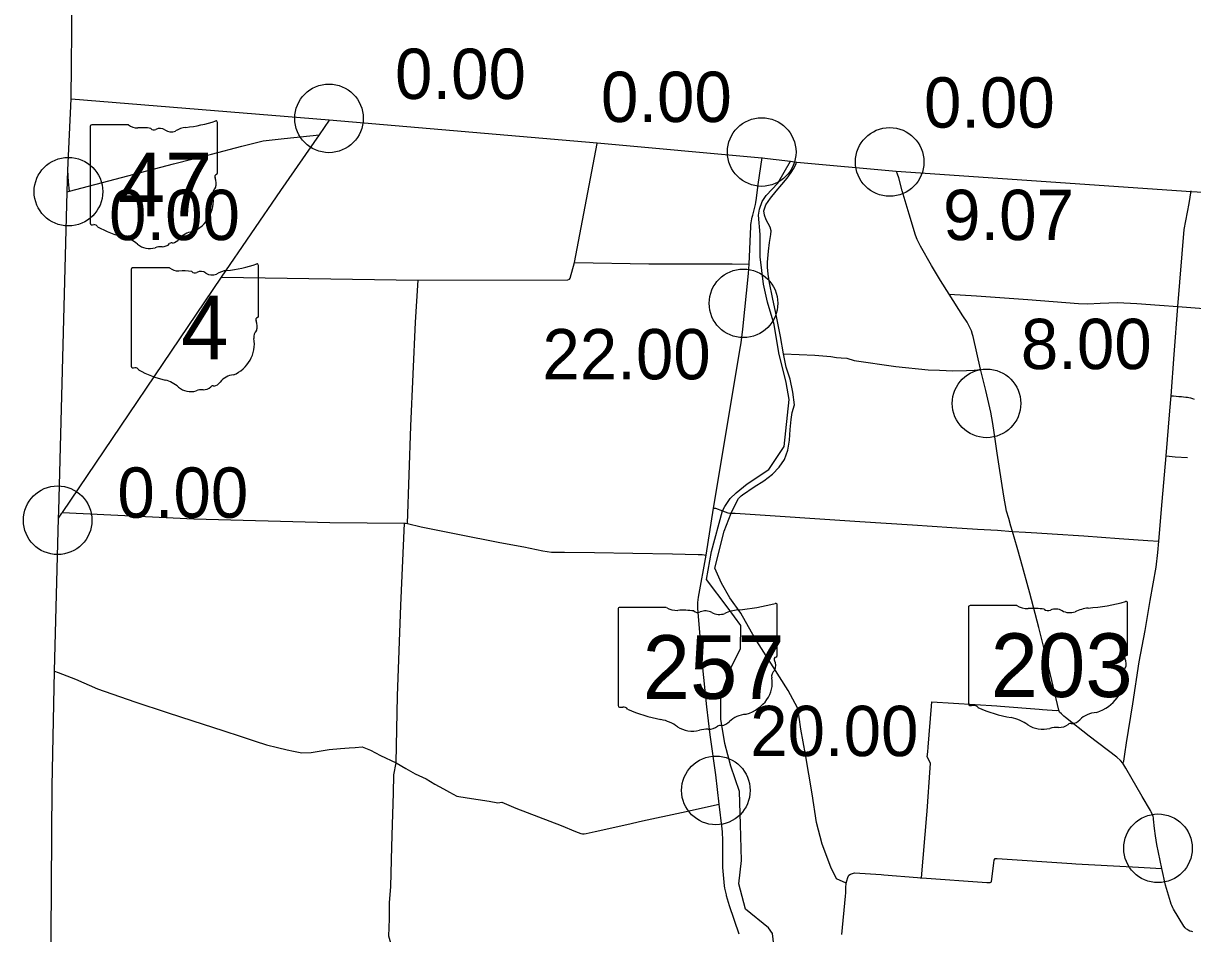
# Model space of a CAD drawing. Extents: x 1729596 to 1934326, y 644115 to 911751.
# Drawn here: x 1759112 to 1784691, y 872786 to 892689 of the extents above; entities that cross this region are included whole.
import ezdxf

# ---------------------------------------------------------------- set-up
doc = ezdxf.new("R2010")
doc.units = 0
for name, color, linetype in [('Default', 7, 'Continuous'), ('GM_X_Adjacent_County', 7, 'Continuous'), ('GM_X_County', 7, 'Continuous'), ('GM_X_County_Road', 7, 'Continuous'), ('GM_X_State_Route', 7, 'Continuous'), ('GM_X_State_Shield', 7, 'Continuous'), ('GM_X_Township', 7, 'Continuous'), ('GM_X_Township_Road', 7, 'Continuous')]:
    doc.layers.add(name, color=color, linetype=linetype)

msp = doc.modelspace()

# ---------------------------------------------------------------- linework, layer by layer
at = {"layer": 'Default'}
for centre in [(1765798, 890612), (1765798, 890612), (1775265, 889876), (1775265, 889876), (1778064, 889660), (1778064, 889660), (1760098, 889010), (1760098, 889010), (1774865, 886568), (1780183, 884380), (1759862, 881825), (1759862, 881825), (1774262, 875917), (1783934, 874652)]:
    msp.add_circle(centre, 750, dxfattribs=at)
at = {"layer": 'GM_X_Adjacent_County'}
msp.add_line((1760161, 891042), (1760364, 911751), dxfattribs=at)
at = {"layer": 'GM_X_County'}
msp.add_lwpolyline([(1759518, 857896), (1759604, 861482), (1759615, 862978), (1759631, 865937), (1759690, 868390), (1759745, 876009), (1759795, 878524), (1759881, 881868), (1759886, 882027), (1760071, 889009), (1760084, 889480), (1760161, 891042), (1765804, 890577), (1771666, 890080), (1775269, 889747), (1775894, 889674), (1776032, 889658), (1778209, 889456), (1784657, 889014), (1789933, 888711), (1791146, 888682), (1797651, 888237), (1803655, 887971)], dxfattribs=at)
at = {"layer": 'GM_X_County_Road'}
for points in [[(1783164, 876512), (1783184, 876554), (1783209, 876711), (1783243, 876961), (1783384, 877811), (1783523, 878729), (1783651, 879411), (1783765, 880071), (1783893, 880796), (1783932, 881116), (1783954, 881366), (1784027, 882233), (1784112, 883231), (1784194, 884219), (1784219, 884544), (1784290, 885451), (1784371, 886499), (1784505, 888183), (1784615, 888751), (1784662, 889026)], [(1779364, 886770), (1779967, 886729), (1781087, 886653), (1782198, 886565), (1782396, 886560), (1782670, 886574), (1783048, 886584), (1783473, 886564), (1783964, 886527), (1784371, 886499), (1786660, 886325), (1787926, 886227), (1788905, 886151), (1789695, 886094), (1789778, 886088), (1790812, 886013), (1791205, 885983), (1792690, 885877), (1793992, 885783), (1794775, 885730), (1796902, 885573), (1797304, 885549), (1797451, 885547), (1797502, 885545)], [(1759969, 881997), (1762841, 881858), (1765814, 881778), (1767451, 881759), (1767471, 881758), (1767516, 881753), (1767813, 881684), (1768617, 881522), (1769536, 881337), (1770062, 881247), (1770477, 881159), (1770666, 881130), (1770953, 881125), (1771606, 881121), (1772443, 881104), (1773313, 881088), (1773587, 881081), (1773877, 881076), (1773962, 881074), (1774048, 881064)], [(1774211, 882090), (1774252, 882089), (1774404, 882033)], [(1774404, 882033), (1774406, 882032), (1774523, 881989), (1774565, 881978), (1774598, 881976), (1774681, 881977), (1777408, 881796), (1778560, 881723), (1779427, 881668), (1779984, 881633), (1780423, 881605), (1780749, 881582)], [(1759795, 878524), (1759874, 878494), (1760252, 878350), (1760733, 878141), (1761552, 877854), (1762256, 877623), (1762819, 877435), (1763473, 877228), (1763875, 877098), (1764180, 876995), (1764428, 876912), (1764673, 876852), (1764882, 876805), (1765024, 876776), (1765203, 876738), (1765411, 876747), (1765804, 876809), (1766052, 876831), (1766236, 876847), (1766368, 876855), (1766526, 876867), (1766703, 876800), (1766927, 876678), (1767271, 876519)], [(1767271, 876519), (1767477, 876397), (1767681, 876278), (1767921, 876172), (1768111, 876051), (1768305, 875950), (1768436, 875882), (1768593, 875793), (1768820, 875758), (1769062, 875716), (1769301, 875685), (1769490, 875642), (1769580, 875657), (1769884, 875528), (1770879, 875150), (1771192, 875019), (1771304, 874972), (1771344, 874966), (1771384, 874967), (1771424, 874974), (1771622, 875018), (1772316, 875174), (1772655, 875249), (1773509, 875437), (1774333, 875620)]]:
    msp.add_lwpolyline(points, dxfattribs=at)
at = {"layer": 'GM_X_State_Route'}
for points in [[(1759881, 881868), (1759956, 881980), (1759969, 881997), (1763443, 887141), (1764744, 889038), (1765591, 890255), (1765808, 890573)], [(1760071, 889009), (1760118, 889022), (1762397, 889618), (1763225, 889831), (1763889, 890004), (1764355, 890118), (1764820, 890175), (1765591, 890255)], [(1774774, 872777), (1774561, 873391), (1774496, 873614), (1774491, 873632), (1774460, 873783), (1774453, 873834), (1774417, 874231), (1774413, 874823), (1774404, 875011), (1774397, 875080), (1774333, 875620), (1774258, 876258), (1774139, 877129), (1774064, 877743), (1773968, 878674), (1773866, 879905), (1773869, 880029), (1773882, 880140), (1774048, 881064), (1774211, 882090), (1774530, 884003), (1774667, 884846), (1774801, 885624), (1774814, 885707), (1774851, 886003), (1774976, 887219), (1774992, 887423), (1775028, 888248), (1775030, 888289), (1775035, 888331), (1775040, 888372), (1775048, 888413), (1775057, 888454), (1775067, 888494), (1775128, 888732), (1775139, 888776), (1775154, 888865), (1775187, 889163), (1775276, 889757)], [(1784699, 872825), (1784673, 872831), (1784633, 872843), (1784596, 872861), (1784578, 872873), (1784561, 872885), (1784531, 872913), (1784502, 872951), (1784275, 873322), (1784260, 873348), (1784235, 873404), (1784225, 873433), (1784211, 873480), (1784162, 873624), (1784100, 873843), (1784021, 874208), (1783910, 874738), (1783876, 874927), (1783859, 875086), (1783838, 875289), (1783833, 875317), (1783827, 875344), (1783809, 875398), (1783786, 875450), (1783772, 875475), (1783588, 875783), (1783232, 876403), (1783164, 876512), (1783115, 876570), (1783035, 876646), (1782427, 877101), (1781907, 877510), (1781873, 877541), (1781822, 877589), (1781780, 877630), (1781764, 877670), (1781516, 878719), (1781330, 879483), (1781130, 880233), (1780935, 880943), (1780851, 881229), (1780749, 881582), (1780714, 881694), (1780668, 881862), (1780620, 882022), (1780562, 882353), (1780462, 883009), (1780418, 883294), (1780375, 883601), (1780321, 883942), (1780275, 884187), (1780166, 884660), (1780054, 885130), (1779891, 885844), (1779879, 885886), (1779851, 885966), (1779818, 886043), (1779756, 886154), (1779666, 886298), (1779364, 886770), (1779176, 887069), (1778977, 887392), (1778738, 887817), (1778667, 887962), (1778627, 888061), (1778487, 888517), (1778336, 889030), (1778262, 889312), (1778237, 889390), (1778211, 889454)]]:
    msp.add_lwpolyline(points, dxfattribs=at)
at = {"layer": 'GM_X_State_Shield'}
for p, q in [((1760571, 890435), (1760571, 888322)), ((1760571, 890435), (1760571, 888322)), ((1761414, 890471), (1760599, 890471)), ((1761414, 890471), (1760599, 890471)), ((1763356, 889418), (1763356, 890524)), ((1763356, 889418), (1763356, 890524)), ((1763355, 889418), (1763356, 889418)), ((1763355, 889418), (1763356, 889418)), ((1762312, 887343), (1761496, 887343)), ((1762312, 887343), (1761496, 887343)), ((1764253, 886290), (1764253, 887395)), ((1764253, 886290), (1764253, 887395)), ((1761469, 887306), (1761469, 885193)), ((1761469, 887306), (1761469, 885193)), ((1764253, 886290), (1764253, 886290)), ((1764253, 886290), (1764253, 886290)), ((1773178, 879920), (1772159, 879920)), ((1773178, 879920), (1772159, 879920)), ((1775605, 878867), (1775605, 879972)), ((1775605, 878867), (1775605, 879972)), ((1779789, 879923), (1779789, 877810)), ((1779789, 879923), (1779789, 877810)), ((1780843, 879960), (1779823, 879960)), ((1780843, 879960), (1779823, 879960)), ((1783269, 878907), (1783269, 880012)), ((1783269, 878907), (1783269, 880012)), ((1772124, 879884), (1772124, 877770)), ((1772124, 879884), (1772124, 877770)), ((1783269, 878907), (1783269, 878907)), ((1783269, 878907), (1783269, 878907)), ((1775604, 878867), (1775605, 878867)), ((1775604, 878867), (1775605, 878867))]:
    msp.add_line(p, q, dxfattribs=at)
for centre, radius, start, end in [((1760603, 890439), 32.3, 98.1301, 188.1301), ((1760603, 890439), 32.3, 98.1301, 188.1301), ((1761608, 890717), 313, 231.6195, 271.1119), ((1761608, 890717), 313, 231.6195, 271.1119), ((1761712, 889285), 1123, 80.4867, 94.9883), ((1761712, 889285), 1123, 80.4867, 94.9883), ((1762741, 889826), 594, 97.3462, 120.7689), ((1762741, 889826), 594, 97.3462, 120.7689), ((1762364, 893352), 2953, 275.8445, 288.9065), ((1762364, 893352), 2953, 275.8445, 288.9065), ((1763325, 890528), 31, 351.8621, 97.738), ((1763325, 890528), 31, 351.8621, 97.738), ((1761967, 890450), 90.3, 219.7921, 297.1024), ((1761967, 890450), 90.3, 219.7921, 297.1024), ((1762100, 890206), 188, 54.4667, 119.1411), ((1762100, 890206), 188, 54.4667, 119.1411), ((1762342, 890541), 226, 233.8562, 294.8282), ((1762342, 890541), 226, 233.8562, 294.8282), ((1763349, 889337), 48, 107.944, 210.337), ((1763349, 889337), 48, 107.944, 210.337), ((1763323, 889414), 33.2, 289.6038, 7.7341), ((1763323, 889414), 33.2, 289.6038, 7.7341), ((1763043, 889197), 288, 340.033, 23.6496), ((1763043, 889197), 288, 340.033, 23.6496), ((1762529, 888815), 739, 292.3089, 8.9858), ((1762529, 888815), 739, 292.3089, 8.9858), ((1763467, 888955), 210, 136.8065, 186.9296), ((1763467, 888955), 210, 136.8065, 186.9296), ((1760604, 888317), 32.5, 171.9584, 258.3066), ((1760604, 888317), 32.5, 171.9584, 258.3066), ((1760609, 888533), 248, 267.339, 280.6039), ((1760609, 888533), 248, 267.339, 280.6039), ((1760659, 888200), 89.5, 29.7484, 93.2717), ((1760659, 888200), 89.5, 29.7484, 93.2717), ((1761790, 890098), 2132, 240.4129, 257.1985), ((1761790, 890098), 2132, 240.4129, 257.1985), ((1762841, 887728), 404, 94.4031, 142.5768), ((1762841, 887728), 404, 94.4031, 142.5768), ((1761154, 887372), 667, 47.1842, 75.836), ((1761154, 887372), 667, 47.1842, 75.836), ((1761876, 888189), 423, 230.7004, 286.2918), ((1761876, 888189), 423, 230.7004, 286.2918), ((1762151, 888031), 226, 268.777, 315.5493), ((1762151, 888031), 226, 268.777, 315.5493), ((1762355, 887826), 63.5, 65.7517, 132.6484), ((1762355, 887826), 63.5, 65.7517, 132.6484), ((1762328, 888117), 239, 282.8732, 323.2771), ((1762328, 888117), 239, 282.8732, 323.2771), ((1762120, 887459), 348, 85.6951, 111.2099), ((1762120, 887459), 348, 85.6951, 111.2099), ((1761501, 887311), 32.3, 98.1301, 188.1301), ((1761501, 887311), 32.3, 98.1301, 188.1301), ((1762506, 887588), 313, 231.6195, 271.1119), ((1762506, 887588), 313, 231.6195, 271.1119), ((1763261, 890224), 2953, 275.8445, 288.9065), ((1763261, 890224), 2953, 275.8445, 288.9065), ((1764222, 887400), 31, 351.8621, 97.738), ((1764222, 887400), 31, 351.8621, 97.738), ((1762610, 886156), 1123, 80.4867, 94.9883), ((1762610, 886156), 1123, 80.4867, 94.9883), ((1762865, 887322), 90.3, 219.7921, 297.1024), ((1762865, 887322), 90.3, 219.7921, 297.1024), ((1762997, 887078), 188, 54.4667, 119.1411), ((1762997, 887078), 188, 54.4667, 119.1411), ((1763239, 887413), 226, 233.8562, 294.8282), ((1763239, 887413), 226, 233.8562, 294.8282), ((1763638, 886697), 594, 97.3462, 120.7689), ((1763638, 886697), 594, 97.3462, 120.7689), ((1764246, 886209), 48, 107.944, 210.337), ((1764246, 886209), 48, 107.944, 210.337), ((1763941, 886069), 288, 340.033, 23.6496), ((1763941, 886069), 288, 340.033, 23.6496), ((1764220, 886285), 33.2, 289.6038, 7.7341), ((1764220, 886285), 33.2, 289.6038, 7.7341), ((1763427, 885686), 739, 292.3089, 8.9858), ((1763427, 885686), 739, 292.3089, 8.9858), ((1764364, 885827), 210, 136.8065, 186.9296), ((1764364, 885827), 210, 136.8065, 186.9296), ((1761501, 885189), 32.5, 171.9584, 258.3066), ((1761501, 885189), 32.5, 171.9584, 258.3066), ((1761506, 885405), 248, 267.339, 280.6039), ((1761506, 885405), 248, 267.339, 280.6039), ((1761557, 885071), 89.5, 29.7484, 93.2717), ((1761557, 885071), 89.5, 29.7484, 93.2717), ((1762687, 886970), 2132, 240.4129, 257.1985), ((1762687, 886970), 2132, 240.4129, 257.1985), ((1762052, 884244), 667, 47.1842, 75.836), ((1762052, 884244), 667, 47.1842, 75.836), ((1763226, 884988), 239, 282.8732, 323.2771), ((1763226, 884988), 239, 282.8732, 323.2771), ((1763738, 884600), 404, 94.4031, 142.5768), ((1763738, 884600), 404, 94.4031, 142.5768), ((1762773, 885061), 423, 230.7004, 286.2918), ((1762773, 885061), 423, 230.7004, 286.2918), ((1763018, 884330), 348, 85.6951, 111.2099), ((1763018, 884330), 348, 85.6951, 111.2099), ((1763049, 884903), 226, 268.777, 315.5493), ((1763049, 884903), 226, 268.777, 315.5493), ((1763253, 884698), 63.5, 65.7517, 132.6484), ((1763253, 884698), 63.5, 65.7517, 132.6484)]:
    msp.add_arc(centre, radius, start, end, dxfattribs=at)
for centre, major_axis, start_param, end_param in [((1772164, 879888), (40.3, 0), 1.712693, 3.28349), ((1772164, 879888), (40.3, 0), 1.712693, 3.28349), ((1773421, 880165), (391, 0), 4.042523, 4.731795), ((1773421, 880165), (391, 0), 4.042523, 4.731795), ((1774365, 882801), (3691, 0), 4.814394, 5.042369), ((1774365, 882801), (3691, 0), 4.814394, 5.042369), ((1775566, 879977), (38.7, 0), 6.141152, 7.989035), ((1775566, 879977), (38.7, 0), 6.141152, 7.989035), ((1779829, 879928), (40.3, 0), 1.712693, 3.28349), ((1779829, 879928), (40.3, 0), 1.712693, 3.28349), ((1781085, 880205), (391, 0), 4.042523, 4.731795), ((1781085, 880205), (391, 0), 4.042523, 4.731795), ((1782030, 882841), (3691, 0), 4.814394, 5.042369), ((1782030, 882841), (3691, 0), 4.814394, 5.042369), ((1783231, 880017), (38.7, 0), 6.141152, 7.989035), ((1783231, 880017), (38.7, 0), 6.141152, 7.989035), ((1773550, 878734), (1404, 0), 1.404758, 1.657858), ((1773550, 878734), (1404, 0), 1.404758, 1.657858), ((1773869, 879899), (113, 0), 3.836095, 5.185415), ((1773869, 879899), (113, 0), 3.836095, 5.185415), ((1774035, 879655), (235, 0), 0.950623, 2.079405), ((1774035, 879655), (235, 0), 0.950623, 2.079405), ((1774337, 879990), (282, 0), 4.081561, 5.145723), ((1774337, 879990), (282, 0), 4.081561, 5.145723), ((1774836, 879275), (743, 0), 1.699011, 2.107814), ((1774836, 879275), (743, 0), 1.699011, 2.107814), ((1781215, 878773), (1404, 0), 1.404758, 1.657858), ((1781215, 878773), (1404, 0), 1.404758, 1.657858), ((1781534, 879939), (113, 0), 3.836095, 5.185415), ((1781534, 879939), (113, 0), 3.836095, 5.185415), ((1781699, 879694), (235, 0), 0.950623, 2.079405), ((1781699, 879694), (235, 0), 0.950623, 2.079405), ((1782002, 880030), (282, 0), 4.081561, 5.145723), ((1782002, 880030), (282, 0), 4.081561, 5.145723), ((1782500, 879314), (743, 0), 1.699011, 2.107814), ((1782500, 879314), (743, 0), 1.699011, 2.107814), ((1783228, 878902), (41.5, 0), 5.05454, 6.418171), ((1783228, 878902), (41.5, 0), 5.05454, 6.418171), ((1775596, 878786), (60, 0), 1.883978, 3.671073), ((1775596, 878786), (60, 0), 1.883978, 3.671073), ((1775214, 878646), (360, 0), 5.934695, 6.695948), ((1775214, 878646), (360, 0), 5.934695, 6.695948), ((1775563, 878863), (41.5, 0), 5.05454, 6.418171), ((1775563, 878863), (41.5, 0), 5.05454, 6.418171), ((1783260, 878825), (60, 0), 1.883978, 3.671073), ((1783260, 878825), (60, 0), 1.883978, 3.671073), ((1782879, 878686), (360, 0), 5.934695, 6.695948), ((1782879, 878686), (360, 0), 5.934695, 6.695948), ((1774572, 878264), (923, 0), 5.101752, 6.440018), ((1774572, 878264), (923, 0), 5.101752, 6.440018), ((1775743, 878404), (262, 0), 2.387724, 3.262537), ((1775743, 878404), (262, 0), 2.387724, 3.262537), ((1782236, 878303), (923, 0), 5.101752, 6.440018), ((1782236, 878303), (923, 0), 5.101752, 6.440018), ((1783408, 878444), (262, 0), 2.387724, 3.262537), ((1783408, 878444), (262, 0), 2.387724, 3.262537), ((1772164, 877766), (40.7, 0), 3.00124, 4.508301), ((1772164, 877766), (40.7, 0), 3.00124, 4.508301), ((1772171, 877982), (310, 0), 4.665946, 4.897461), ((1772171, 877982), (310, 0), 4.665946, 4.897461), ((1772234, 877649), (112, 0), 0.519207, 1.627899), ((1772234, 877649), (112, 0), 0.519207, 1.627899), ((1773647, 879547), (2665, 0), 4.195997, 4.488961), ((1773647, 879547), (2665, 0), 4.195997, 4.488961), ((1779829, 877805), (40.7, 0), 3.00124, 4.508301), ((1779829, 877805), (40.7, 0), 3.00124, 4.508301), ((1779835, 878022), (310, 0), 4.665946, 4.897461), ((1779835, 878022), (310, 0), 4.665946, 4.897461), ((1779899, 877688), (112, 0), 0.519207, 1.627899), ((1779899, 877688), (112, 0), 0.519207, 1.627899), ((1781312, 879587), (2665, 0), 4.195997, 4.488961), ((1781312, 879587), (2665, 0), 4.195997, 4.488961), ((1782626, 877217), (506, 0), 1.647645, 2.488434), ((1782626, 877217), (506, 0), 1.647645, 2.488434), ((1772853, 876821), (834, 0), 0.823519, 1.323587), ((1772853, 876821), (834, 0), 0.823519, 1.323587), ((1774320, 877566), (298, 0), 4.937069, 5.64225), ((1774320, 877566), (298, 0), 4.937069, 5.64225), ((1774961, 877177), (506, 0), 1.647645, 2.488434), ((1774961, 877177), (506, 0), 1.647645, 2.488434), ((1780518, 876861), (834, 0), 0.823519, 1.323587), ((1780518, 876861), (834, 0), 0.823519, 1.323587), ((1781764, 877519), (282, 0), 4.691044, 5.507374), ((1781764, 877519), (282, 0), 4.691044, 5.507374), ((1782019, 877315), (79.4, 0), 1.147584, 2.315152), ((1782019, 877315), (79.4, 0), 1.147584, 2.315152), ((1781985, 877605), (298, 0), 4.937069, 5.64225), ((1781985, 877605), (298, 0), 4.937069, 5.64225), ((1773755, 877638), (529, 0), 4.026481, 4.996735), ((1773755, 877638), (529, 0), 4.026481, 4.996735), ((1774060, 876907), (435, 0), 1.495662, 1.94098), ((1774060, 876907), (435, 0), 1.495662, 1.94098), ((1774099, 877480), (282, 0), 4.691044, 5.507374), ((1774099, 877480), (282, 0), 4.691044, 5.507374), ((1774354, 877275), (79.4, 0), 1.147584, 2.315152), ((1774354, 877275), (79.4, 0), 1.147584, 2.315152), ((1781419, 877678), (529, 0), 4.026481, 4.996735), ((1781419, 877678), (529, 0), 4.026481, 4.996735), ((1781725, 876947), (435, 0), 1.495662, 1.94098), ((1781725, 876947), (435, 0), 1.495662, 1.94098)]:
    msp.add_ellipse(centre, major_axis=major_axis, ratio=0.8, start_param=start_param, end_param=end_param, dxfattribs=at)
at = {"layer": 'GM_X_Township'}
msp.add_lwpolyline([(1775561, 872294), (1775504, 872788), (1775414, 872915), (1774908, 873319), (1774761, 873873), (1774819, 874386), (1774803, 875172), (1774782, 875893), (1774586, 876451), (1774457, 876944), (1774369, 877473), (1774370, 877987), (1774561, 878529), (1774803, 879020), (1774811, 879521), (1774533, 879901), (1774059, 880530), (1774167, 881144), (1774406, 882032), (1774456, 882123), (1774578, 882303), (1774707, 882427), (1774948, 882624), (1775424, 882934), (1775526, 883091), (1775753, 883439), (1775862, 884465), (1775797, 884834), (1775636, 885483), (1775537, 886105), (1775391, 886594), (1775307, 886986), (1775234, 887582), (1775230, 888073), (1775193, 888494), (1775219, 888624), (1775271, 888791), (1775360, 888928), (1775618, 889192), (1775894, 889674)], dxfattribs=at)
at = {"layer": 'GM_X_Township_Road'}
for points in [[(1763443, 887141), (1767751, 887076), (1767754, 887076), (1771026, 887079), (1771060, 887099), (1771076, 887115), (1771171, 887463), (1771666, 890061)], [(1774598, 881976), (1774720, 882234), (1774760, 882299), (1774813, 882356), (1774843, 882381), (1775103, 882554), (1775313, 882683), (1775499, 882831), (1775649, 882983), (1775766, 883156), (1775837, 883357), (1775874, 883577), (1775887, 883810), (1775907, 884030), (1775933, 884182), (1775979, 884346), (1775947, 884626), (1775885, 884907), (1775798, 885171), (1775741, 885463), (1775674, 885840), (1775571, 886351), (1775497, 886692), (1775435, 887014), (1775403, 887209), (1775389, 887360), (1775389, 887468), (1775413, 887707), (1775432, 887898), (1775464, 888072), (1775469, 888156), (1775448, 888237), (1775365, 888393), (1775328, 888495), (1775314, 888590), (1775354, 888724), (1775454, 888867), (1775584, 889017), (1775702, 889168), (1775820, 889307), (1775910, 889426), (1775960, 889506), (1776017, 889615), (1776026, 889659)], [(1760118, 889022), (1760097, 889226), (1760084, 889480)], [(1771171, 887463), (1772796, 887430), (1772896, 887428), (1774620, 887429), (1774992, 887423)], [(1767516, 881753), (1767592, 883879), (1767693, 886154), (1767751, 887076)], [(1775741, 885463), (1776426, 885437), (1776777, 885403), (1776902, 885381), (1777004, 885378), (1777125, 885372), (1777289, 885315), (1778196, 885185), (1778905, 885114), (1779153, 885103), (1779444, 885093), (1779746, 885100), (1779909, 885109), (1779987, 885117), (1780054, 885130)], [(1784219, 884544), (1784275, 884542), (1784330, 884538), (1784387, 884534), (1784447, 884529), (1784491, 884526), (1784544, 884519), (1784576, 884515), (1784610, 884507), (1784645, 884498), (1784687, 884486), (1784724, 884474)], [(1784112, 883231), (1784306, 883215), (1784581, 883194)], [(1777019, 872766), (1777098, 873608), (1777104, 873680), (1777108, 873786), (1777112, 873891), (1776901, 873984), (1776777, 874239), (1776590, 874743), (1776465, 875214), (1776369, 875841), (1776222, 876705), (1776122, 877260), (1776082, 877522), (1776051, 877721), (1775845, 878101), (1775513, 878619), (1775109, 879262), (1774809, 879796), (1774568, 880125), (1774383, 880446), (1774238, 880775), (1774441, 881584), (1774598, 881976)], [(1767271, 876519), (1767296, 877988), (1767372, 879961), (1767451, 881759)], [(1780749, 881582), (1781033, 881565), (1781283, 881552), (1781619, 881527), (1782312, 881487), (1783082, 881429), (1783715, 881383), (1783954, 881366)], [(1778760, 874006), (1778875, 875382), (1778882, 875465), (1778952, 876413), (1778959, 876509), (1778911, 876603), (1778883, 876655), (1778897, 876760), (1778909, 876862), (1778976, 877757), (1778983, 877852), (1780406, 877766), (1780489, 877760), (1781332, 877695), (1781408, 877688), (1781724, 877665), (1781764, 877670)], [(1768190, 870136), (1768081, 870244), (1767947, 870409), (1767861, 870528), (1767742, 870726), (1767651, 870916), (1767543, 871171), (1767459, 871342), (1767376, 871496), (1767334, 871653), (1767253, 872089), (1767171, 872502), (1767108, 872731), (1767120, 873106), (1767121, 873461), (1767150, 873817), (1767171, 874681), (1767185, 875170), (1767198, 875395), (1767211, 875858), (1767213, 876255), (1767271, 876519)], [(1778734, 874009), (1778760, 874006), (1778766, 874006), (1780188, 873906), (1780264, 873900), (1780288, 873916), (1780344, 874335), (1780352, 874393), (1780370, 874430), (1780414, 874432), (1782047, 874317), (1782140, 874310), (1783379, 874247), (1784021, 874208)], [(1777112, 873891), (1777129, 873941), (1777152, 874011), (1777174, 874061), (1777204, 874087), (1777296, 874115), (1777876, 874078), (1777937, 874074), (1778674, 874014), (1778730, 874009), (1778734, 874009)]]:
    msp.add_lwpolyline(points, dxfattribs=at)

# ---------------------------------------------------------------- texts
at = {"layer": 'Default'}
for s, p in [('0.00', (1767243, 891037)), ('0.00', (1771748, 890533)), ('0.00', (1778814, 890410)), ('0.00', (1760987, 887951)), ('9.07', (1779232, 887951)), ('8.00', (1780933, 885130)), ('22.00', (1770467, 884906)), ('0.00', (1761169, 881879)), ('20.00', (1775012, 876667))]:
    msp.add_text(s, height=1100, dxfattribs=at).set_placement(p)
at = {"layer": 'GM_X_State_Shield'}
for s, height, p in [('47', 1392.2, (1761177, 888471)), ('47', 1392.2, (1761177, 888471)), ('4', 1392, (1762565, 885342)), ('4', 1392, (1762565, 885342)), ('257', 1392.2, (1772660, 877919)), ('257', 1392.2, (1772660, 877919)), ('203', 1392.2, (1780274, 877959)), ('203', 1392.2, (1780274, 877959))]:
    msp.add_text(s, height=height, dxfattribs=at).set_placement(p)

doc.saveas('drawing.dxf')
